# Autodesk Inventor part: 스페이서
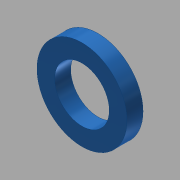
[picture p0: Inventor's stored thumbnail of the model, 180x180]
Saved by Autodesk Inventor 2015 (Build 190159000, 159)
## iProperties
Created: 2018-01
Part Number: 스페이서
Material: 스테인리스강
Document SubType Name: Modeling
Designer: mduedu
Density: 8.08 g/cm^3
Appearance: 청록색
Mass: 1.9633 g
Surface Area: 3.71101 cm^2
Volume: 0.242983 cm^3
Author: mduedu
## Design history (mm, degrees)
sketch "스케치1"
  geometry: C1 r 7 at (0, 0); C2 r 4.25 at (0, 0); 1 further point
  constraints: 2 centre point, 2 coincident
  dimensions: "d0" = 14 diameter of C1; "d1" = 8.5 diameter of C2
extrude "돌출1" new body sketch "스케치1" distance "d2" = 2.5; taper "d3" = 0 deg
node "솔리드1"
